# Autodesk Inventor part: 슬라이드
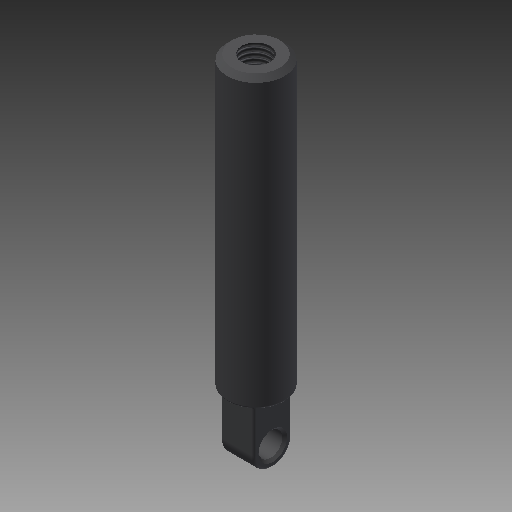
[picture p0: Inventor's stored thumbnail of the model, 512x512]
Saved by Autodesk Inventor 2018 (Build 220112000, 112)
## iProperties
Created: 2016-02
Part Number: 슬라이드
Material: 강철, 연강
Document SubType Name: Modeling
Designer: test
Density: 1 g/cm^3
Appearance: 회색
Author: test
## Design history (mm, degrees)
sketch "스케치2"
  geometry: C1 r 6 at (0, 0); 1 further point
  constraints: 1 centre point, 1 coincident
  dimensions: "d0" = 12 diameter of C1
extrude "돌출1" new body sketch "스케치2" distance "d1" = 60; taper "d2" = 0 deg
hole "구멍1" diameter "d5" = 5.917; stored, may be unused: countersink angle "d9" = 90 deg, drill point angle "d11" = 118 deg; dims "d3" = 10, "d4" = 10, "d6" = 10, "d7" = 4, "d8" = 2, "d10" = 12
chamfer "모따기1" distance "d12" = 1; stored, may be unused: second distance "d13" = 2, angle "d14" = 45 deg
sketch "스케치3"
  geometry: L1 (0, 6)-(0, -6) reference; L2 (0, 4)-(-9, 4); L3 (-9, -4)-(0, -4); L4 (0, -4)-(0, 4); C1 r 2.5 at (-9, 0); A1 r 4 centre (-9, 0) between (-9, 4) and (-9, -4); 2 further points
  constraints: 6 end point, 2 centre point, 2 point on circle, 2 tangent, 1 coincident, 1 horizontal, 1 horizontal alignment, 1 midpoint, 1 parallel, 1 point on line, 1 vertical
  dimensions: "d15" = 13 dimension on A1 L1; "d16" = 8 distance between parallel lines of L3 L2; "d17" = 5 diameter of C1
extrude "돌출2" join sketch "스케치3" stored distance "d18" = 7; taper "d19" = 0 deg
chamfer "모따기2" distance "d20" = 0.5; stored, may be unused: second distance "d21" = 2, angle "d22" = 45 deg
fillet "모깎기1" dims "d23" = 0.5
fillet "모깎기2" dims "d24" = 0.5
fillet "모깎기3" dims "d25" = 0.5
node "솔리드1"
